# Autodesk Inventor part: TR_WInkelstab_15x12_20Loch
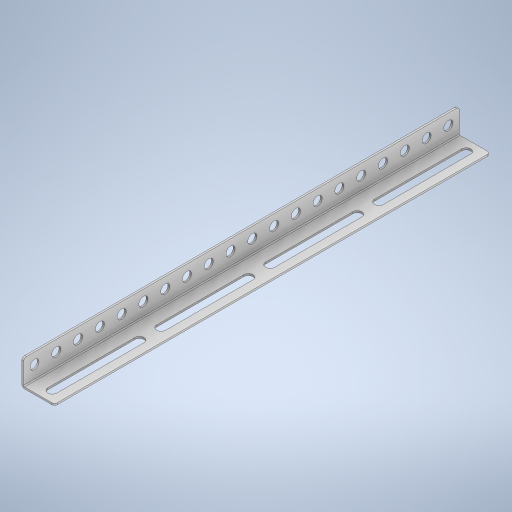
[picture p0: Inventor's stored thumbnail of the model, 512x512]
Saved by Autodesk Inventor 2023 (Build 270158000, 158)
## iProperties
Created: 2023-11
Part Number: TR_WInkelstab_15x12_20Loch
Material: Generisch
Document SubType Name: Modeling
Designer: Administrator
Density: 1 g/cm^3
Appearance: Vorgabe
Author: Administrator
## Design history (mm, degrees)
sketch "Skizze1"
  geometry: L1 (0, 12)-(0, 1.25); L2 (1.25, 0)-(15, 0); L3 (15, 0)-(15, 0.8); L4 (15, 0.8)-(1.25, 0.8); L5 (0.8, 1.25)-(0.8, 12); L6 (0.8, 12)-(0, 12); A1 r 1.25 centre (1.25, 1.25) between (0, 1.25) and (1.25, 0); A2 r 0.45 centre (1.25, 1.25) between (0.8, 1.25) and (1.25, 0.8); 1 further point
  constraints: 12 end point, 5 perpendicular, 4 point on circle, 4 tangent, 2 centre point, 2 point on line, 1 coincident, 1 vertical
  dimensions: "d0" = 1.25 radius of A1; "d2" = 0.8 distance of L5.end L1.start (= Dicke); "d3" = 12 distance of point (0, 0) L1.start; "d4" = 15 distance of point (0, 0) L2.end
extrude "Extrusion1" new body sketch "Skizze1" stored distance "d5" = 200 (computed from Lochzahl, Einheitsmaß); taper "d6" = 0 deg
sketch "Skizze2"
  geometry: L1 (7.75, 5)-(7.75, 45); L2 (9.825, 5)-(9.825, 45); L3 (5.675, 45)-(5.675, 5); L4 (13.75, 200)-(13.75, 0) reference; L5 (13.75, 0)-(0, 0) reference; A1 r 2.075 centre (7.75, 5) between (5.675, 5) and (9.825, 5); A2 r 2.075 centre (7.75, 45) between (9.825, 45) and (5.675, 45); 3 further points
  constraints: 8 end point, 4 point on circle, 4 tangent, 2 centre point, 2 midpoint, 1 parallel, 1 vertical
  dimensions: "d8" = 4.15 diameter of A2 (= 2 x Radius); "d9" = 40 distance of L1.start L1.end (= Langloch); "d10" = 6 distance from line of L4 L1.start; "d11" = 5 vertical distance of point (6.875, 0) L1.start (= 0.5 x Einheitsmaß)
extrude "Extrusion2" cut sketch "Skizze2" extent not by distance; stored distance "d12" = 0; taper "d13" = 0 deg
sketch "Skizze3"
  geometry: L1 (0, 10.75)-(200, 10.75) reference; L2 (0, 0)-(0, 10.75) reference; C1 r 2.075 at (5, 5.75); 1 further point
  constraints: 1 centre point
  dimensions: "d14" = 4.15 diameter of C1 (= 2 x Radius); "d15" = 5 distance from line of C1.centre L1 (= 0.5 x Einheitsmaß); "d16" = 5 distance from line of C1.centre L2 (= 0.5 x Einheitsmaß)
extrude "Extrusion3" cut sketch "Skizze3" extent not by distance; stored distance "d17" = 0; taper "d18" = 0 deg
fillet "Rundung1" dims "d22" = 1.25
pattern_linear "Rechteckige Anordnung2" dims "d25" = 50 (computed from Einheitsmaß, Lochzahl)
node "Volumenkörper1"
pattern_linear "Rechteckige Anordnung1" dims "d21" = 10 (= Einheitsmaß)
other parameters: "Einheitsmaß" = 10 [user parameter; used in 6 equation terms], "Radius" = 2.075 [user parameter; used in 2 equation terms], "Fasen" = 0.5 [user parameter], "Dicke" = 0.8 [user parameter; used in 1 equation term], "Breitloch" = 2 [user parameter], "Langloch" = 40 [user parameter; used in 1 equation term], "AchteckUmkreis" = 6 [user parameter], "DAchsAufnahme" = 4.1 [user parameter], "AchsDurchmesser" = 4 [user parameter], "AchsFase" = 0.5 [user parameter]
